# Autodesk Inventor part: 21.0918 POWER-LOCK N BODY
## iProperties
Created: 2006-12
Part Number: 21.0918 POWER-LOCK N BODY
Document SubType Name: Modeling
Designer: Andy Moles
Material: Steel
Mass: 25.5625 g
Surface Area: 20.514 cm^2
Volume: 3.25636 cm^3
Density: 7.85 g/cm^3
Author: Andy Moles
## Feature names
1. Extrusion1
2. Extrusion2
3. Extrusion3
4. Chamfer1
5. Chamfer2
6. Extrusion4
7. Mirror1
8. Extrusion5
9. Hole1
10. Hole2
